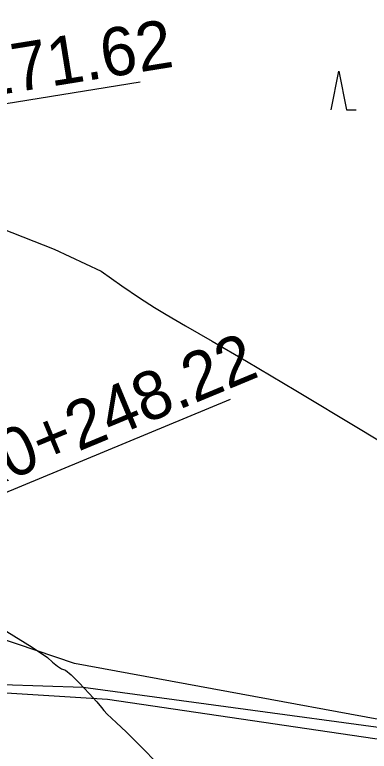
# Model space of a CAD drawing. Extents: x -574342 to -508101, y -1143544 to -1123894.
# Drawn here: x -508523.81 to -508505.49, y -1143258.4 to -1143220.32 of the extents above; entities that cross this region are included whole.
import ezdxf

# ---------------------------------------------------------------- set-up
doc = ezdxf.new("R2010")
doc.units = 0
for name, color, linetype in [('01_PARCELY_NAVRH_PC', 7, 'Continuous'), ('18', 7, 'Continuous'), ('23', 7, 'Continuous'), ('42', 7, 'Continuous'), ('43', 7, 'Continuous'), ('55', 7, 'Continuous'), ('VRST HL', 7, 'Continuous'), ('VRST VEDL', 7, 'Continuous')]:
    doc.layers.add(name, color=color, linetype=linetype)

msp = doc.modelspace()

# ---------------------------------------------------------------- linework, layer by layer
at = {"layer": '01_PARCELY_NAVRH_PC'}
msp.add_lwpolyline([(-508446.21, -1143255.76), (-508469.74, -1143257.73), (-508480.76, -1143258.08), (-508496.39, -1143258.35), (-508520.28, -1143255.11), (-508526.55, -1143254.9), (-508531.16, -1143250.06), (-508524.26, -1143263.08), (-508521.01, -1143259.29), (-508514.56, -1143259.91), (-508493.5, -1143263.3), (-508475.11, -1143263.39), (-508446.02, -1143260.22)], close=True, dxfattribs=at)
at = {"layer": '23'}
for points in [[(-508543.975, -1143228.097), (-508517.319, -1143223.8)], [(-508537.597, -1143250.55), (-508512.663, -1143240.191)]]:
    msp.add_lwpolyline(points, dxfattribs=at)
at = {"layer": '42'}
msp.add_lwpolyline([(-508475.71, -1143257.35), (-508496.39, -1143258.35), (-508520.72, -1143253.86), (-508528.66, -1143251.18), (-508534.38, -1143238.75), (-508538.15, -1143218.95), (-508538.33, -1143193.52)], dxfattribs=at)
msp.add_lwpolyline([(-508475.71, -1143257.35), (-508496.39, -1143258.35), (-508520.72, -1143253.86), (-508528.66, -1143251.18), (-508534.38, -1143238.75), (-508538.15, -1143218.95), (-508538.33, -1143193.52)], dxfattribs=at)
at = {"layer": '43'}
for p, q in [((-508507.46, -1143225.243), (-508507.06, -1143223.243)), ((-508507.06, -1143223.243), (-508506.66, -1143225.243)), ((-508506.66, -1143225.243), (-508506.16, -1143225.243))]:
    msp.add_line(p, q, dxfattribs=at)
at = {"layer": '55'}
msp.add_lwpolyline([(-508530.09, -1143253.58), (-508526.75, -1143255.23), (-508519.02, -1143255.71), (-508495.48, -1143259.17)], dxfattribs=at)
msp.add_lwpolyline([(-508530.09, -1143253.58), (-508526.75, -1143255.23), (-508519.02, -1143255.71), (-508495.48, -1143259.17)], dxfattribs=at)
at = {"layer": 'VRST HL'}
msp.add_lwpolyline([(-508524.215, -1143252.216), (-508522.909, -1143253.02), (-508522.122, -1143253.549), (-508521.851, -1143253.802), (-508521.606, -1143253.997), (-508521.386, -1143254.134), (-508521.19, -1143254.213), (-508520.887, -1143254.453), (-508520.477, -1143254.854), (-508519.959, -1143255.417), (-508519.574, -1143255.846), (-508519.321, -1143256.14), (-508519.201, -1143256.3), (-508519.031, -1143256.485), (-508518.812, -1143256.694), (-508518.545, -1143256.928), (-508518.051, -1143257.403), (-508517.331, -1143258.121), (-508516.385, -1143259.08)], dxfattribs=at)
at = {"layer": 'VRST VEDL'}
msp.add_lwpolyline([(-508525.588, -1143230.947), (-508521.778, -1143232.443), (-508519.338, -1143233.572), (-508518.27, -1143234.334), (-508517.355, -1143234.962), (-508516.593, -1143235.456), (-508515.986, -1143235.816), (-508514.99, -1143236.399), (-508513.606, -1143237.206), (-508511.834, -1143238.236), (-508509.285, -1143239.75), (-508505.958, -1143241.749), (-508501.854, -1143244.233)], dxfattribs=at)

# ---------------------------------------------------------------- texts
at = {"layer": '18'}
for s, rotation, p in [('KT0+271.62', 9.1564, (-508533.586, -1143225.916)), ('TK0+248.22', 22.5603, (-508527.996, -1143246.019))]:
    msp.add_text(s, height=2.5, rotation=rotation, dxfattribs=at).set_placement(p)

doc.saveas('drawing.dxf')
